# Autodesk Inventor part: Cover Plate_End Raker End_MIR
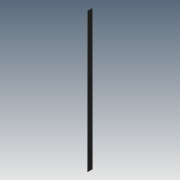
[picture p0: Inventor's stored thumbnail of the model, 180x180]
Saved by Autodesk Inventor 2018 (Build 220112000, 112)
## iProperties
Created: 2018-02
Part Number: Cover Plate_End Raker End_MIR
Material: Steel, Mild
Document SubType Name: Sheet Metal
Designer: STK
Density: 7.85 g/cm^3
Sheet Metal Rule: Default
Appearance: Semi-Polished
Mass: 228301 g
Surface Area: 93127.2 cm^2
Volume: 29082.9 cm^3
Author: STK
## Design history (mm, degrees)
derived "Cover Plate_End Raker End.ipt"
  sketch "Sketch1"
    geometry: L1 (-5816.6, 196.85)-(5816.6, 196.85) reference; L2 (5816.6, 196.85)-(5816.6, -196.85) reference; L3 (5816.6, -196.85)-(-5816.6, -196.85) reference; L4 (-5816.6, -196.85)-(-5816.6, 196.85) reference; L5 (-5816.6, 196.85)-(5816.6, -196.85) reference; L6 (5816.6, 196.85)-(-5816.6, -196.85) reference; 1 further point
feature "Solid1::Cover Plate_End Raker End.ipt" dims "d0" = 10
tag "TaggingFeature1"
body "Solid1"
other parameters: "Thickness" = 3.048, "BendRadius" = 3.048 (= Thickness), "BendReliefWidth" = 3.048 (= Thickness), "BendReliefDepth" = 1.524 (= 0.5 x Thickness), "CornerReliefSize" = 12.192 (= 4 x Thickness), "SeamGap" = 0.00508, "MinimumRemnant" = 6.096 (= 2 x Thickness), "TransitionRadius" = 3.048 (= BendRadius), "JacobiRadiusSize" = 3.048 (= BendRadius), "GapSize" = 3.048 (= Thickness)
